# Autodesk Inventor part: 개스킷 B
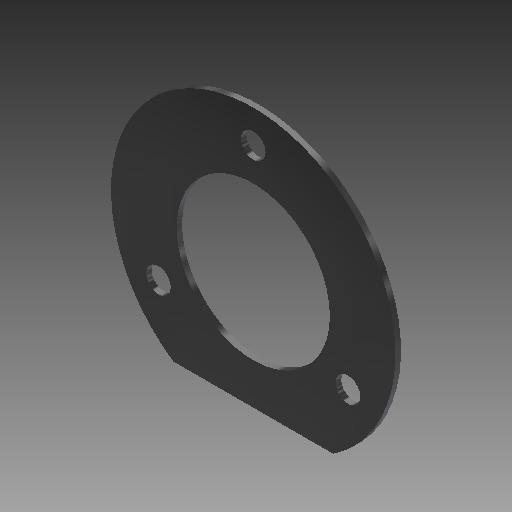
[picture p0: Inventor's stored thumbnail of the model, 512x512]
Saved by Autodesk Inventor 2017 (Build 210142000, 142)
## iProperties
Created: 2020-04
Part Number: 개스킷 B
Material: 고무
Document SubType Name: Modeling
Designer: mduedu
Density: 1 g/cm^3
Appearance: 고무 - 검은색 - 버전 1.1
Author: mduedu
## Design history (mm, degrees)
sketch "스케치1"
  geometry: C1 r 26 at (0, 0); 1 further point
  constraints: 1 centre point, 1 coincident
  dimensions: "d0" = 52 diameter of C1
extrude "돌출1" new body sketch "스케치1" distance "d1" = 1; taper "d2" = 0 deg
sketch "스케치2"
  geometry: L1 (-14.62, -21.5)-(14.62, -21.5); A1 r 26 centre (0, 0) between (-14.62, -21.5) and (14.62, -21.5) reference; 1 further point
  constraints: 2 end point, 2 point on circle, 1 horizontal
  dimensions: "d3" = 21.5 distance from line of L1 point (0, 0)
extrude "돌출2" cut sketch "스케치2" stored distance "d4" = 1; taper "d5" = 0 deg
sketch "스케치3" dims "d6" = 40
  geometry: 3 further points
  constraints: 2 vertical alignment, 1 coincident, 2 other
hole "구멍1" sketch "스케치3" at (0, 20) diameter "d7" = 4.5; stored, may be unused: countersink angle "d11" = 90 deg, drill point angle "d13" = 118 deg; dims "d8" = 6, "d9" = 4, "d10" = 2, "d12" = 8
sketch "스케치4"
  geometry: C1 r 14 at (0, 0); 1 further point
  constraints: 1 centre point, 1 coincident
  dimensions: "d17" = 28 diameter of C1
extrude "돌출3" cut sketch "스케치4" stored distance "d18" = 1; taper "d19" = 0 deg
node "솔리드1"
pattern_circular "원형 패턴1" dims angle "d15" = 360 deg
node "투영된 루프1"
